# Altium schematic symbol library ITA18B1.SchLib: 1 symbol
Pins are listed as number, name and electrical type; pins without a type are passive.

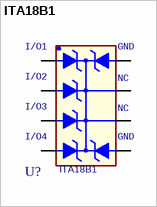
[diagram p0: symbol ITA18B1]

## ITA18B1
designator U?
footprint ST_SO8
pins: 1 I/O1, 2 I/O2, 3 I/O3, 4 I/O4, 5 GND, 6 NC, 7 NC1, 8 GND1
